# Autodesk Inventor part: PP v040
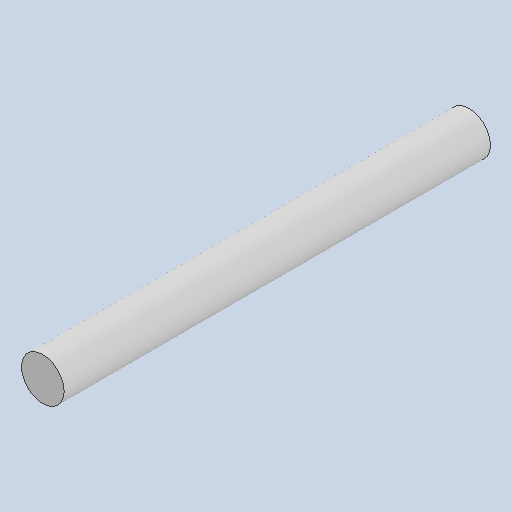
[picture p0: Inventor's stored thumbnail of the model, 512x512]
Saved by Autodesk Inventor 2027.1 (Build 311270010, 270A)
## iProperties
Created: 2026-10
Part Number: PP v040
Material: Generic
Document SubType Name: Modeling
Designer: niels
Density: 1 g/cm^3
Appearance: Default
Author: niels
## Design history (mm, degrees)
sketch "Sketch1"
  geometry: C1 r 50 at (0, 0)
  constraints: 1 centre point, 1 other
  dimensions: "D" = 100 diameter of C1
extrude "Extrusion1" new body sketch "Sketch1" distance "d1" = 1000; taper "d2" = 0 deg
node "Air"
